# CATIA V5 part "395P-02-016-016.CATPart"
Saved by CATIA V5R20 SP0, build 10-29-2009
Part number: 395P-02-016-016
Definition: NONE
Nomenclature: 395P-02-016-016
Source: Unknown
Description: PART-_395P-02-016-016-DESC
Bounding box of the stored display mesh (mm): x -12 to 12, y -28 to 30, z -13.856 to 13.856
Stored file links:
  C:\Users\Utente\Desktop\3D files 395P\395P-02-016-016.CATPart
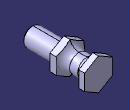
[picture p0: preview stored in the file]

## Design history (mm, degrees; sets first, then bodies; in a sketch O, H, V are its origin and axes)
Body1 "395P-02-016-016" (main body)
  Solid1: solid without history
